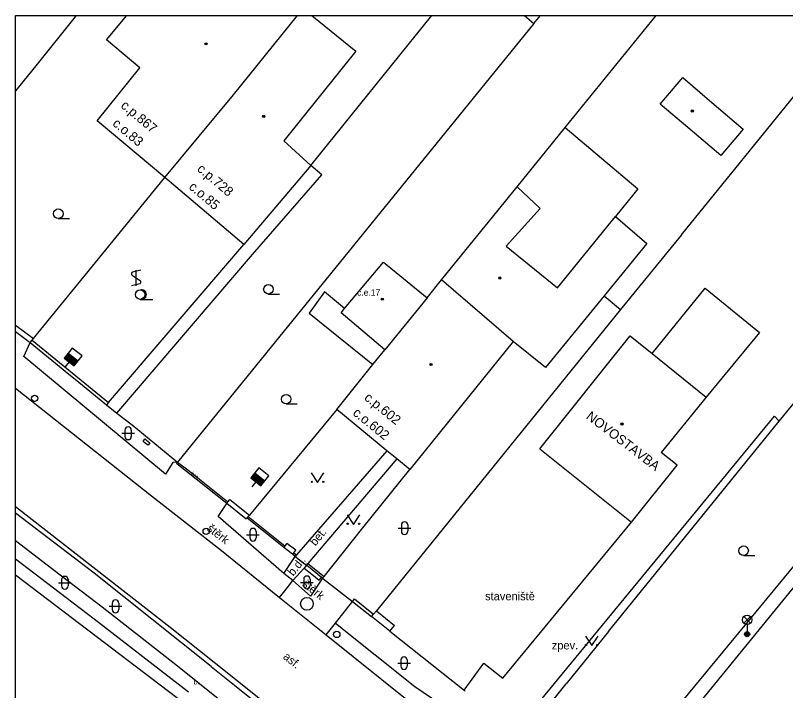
# Model space of a CAD drawing. Extents: x -594386 to -594050, y -1167541 to -1167175.
# Drawn here: x -594386.4 to -594325.8, y -1167228.4 to -1167175.4 of the extents above; entities that cross this region are included whole.
import ezdxf

# ---------------------------------------------------------------- set-up
doc = ezdxf.new("R2010")
doc.units = 0
for name, color, linetype in [('Level 14', 7, 'Continuous'), ('Level 24', 7, 'Continuous'), ('Level 27', 7, 'Continuous'), ('Level 28', 7, 'Continuous'), ('Level 33', 7, 'Continuous'), ('Level 36', 7, 'Continuous'), ('Level 39', 7, 'Continuous'), ('Level 41', 7, 'Continuous'), ('Vrstva 10', 7, 'Continuous'), ('Vrstva 11', 7, 'Continuous'), ('Vrstva 40', 7, 'Continuous'), ('Vrstva 42', 7, 'Continuous'), ('Vrstva 46', 7, 'Continuous'), ('Vrstva 5', 7, 'Continuous'), ('Vrstva 51', 7, 'Continuous'), ('Vrstva 52', 7, 'Continuous'), ('Vrstva 63', 7, 'Continuous'), ('Vrstva 7', 7, 'Continuous'), ('Vrstva 8', 7, 'Continuous')]:
    doc.layers.add(name, color=color, linetype=linetype)

msp = doc.modelspace()

# ---------------------------------------------------------------- linework, layer by layer
at = {"layer": 'Level 14'}
for points in [[(-594373.63, -1167226.53), (-594379.54, -1167221.89), (-594382.84, -1167219.37), (-594386.36, -1167216.691)], [(-594372.76, -1167228.57), (-594380.18, -1167222.84), (-594382.36, -1167221.16), (-594386.36, -1167218.111)], [(-594353.85, -1167242.33), (-594359.75, -1167237.6), (-594370.16, -1167229.3), (-594373.63, -1167226.53)]]:
    msp.add_lwpolyline(points, dxfattribs=at)
at = {"layer": 'Level 24'}
for points in [[(-594363.49, -1167218.6), (-594363.67, -1167218.83)], [(-594363.67, -1167218.83), (-594363.08, -1167219.3), (-594362.49, -1167219.78), (-594362.31, -1167219.55)], [(-594362.31, -1167219.55), (-594363.49, -1167218.6)]]:
    msp.add_lwpolyline(points, dxfattribs=at)
at = {"layer": 'Level 27'}
msp.add_circle((-594363.46, -1167221.63), 0.5, dxfattribs=at)
at = {"layer": 'Level 28'}
for p, q in [((-594382.252, -1167201.977), (-594381.47, -1167202.601)), ((-594382.221, -1167201.938), (-594381.439, -1167202.562)), ((-594382.502, -1167202.29), (-594381.72, -1167202.914)), ((-594382.47, -1167202.251), (-594381.689, -1167202.875)), ((-594382.439, -1167202.212), (-594381.658, -1167202.835)), ((-594382.408, -1167202.172), (-594381.626, -1167202.796)), ((-594382.377, -1167202.133), (-594381.595, -1167202.757)), ((-594382.346, -1167202.094), (-594381.564, -1167202.718)), ((-594382.314, -1167202.055), (-594381.533, -1167202.679)), ((-594382.283, -1167202.016), (-594381.502, -1167202.64)), ((-594382.142, -1167202.641), (-594382.473, -1167203.055)), ((-594367.822, -1167211.69), (-594367.04, -1167212.314)), ((-594367.79, -1167211.651), (-594367.009, -1167212.275)), ((-594367.759, -1167211.612), (-594366.978, -1167212.235)), ((-594367.728, -1167211.572), (-594366.946, -1167212.196)), ((-594367.697, -1167211.533), (-594366.915, -1167212.157)), ((-594367.666, -1167211.494), (-594366.884, -1167212.118)), ((-594367.634, -1167211.455), (-594366.853, -1167212.079)), ((-594367.603, -1167211.416), (-594366.822, -1167212.04)), ((-594367.572, -1167211.377), (-594366.79, -1167212.001)), ((-594367.541, -1167211.338), (-594366.759, -1167211.962)), ((-594367.462, -1167212.041), (-594367.793, -1167212.455))]:
    msp.add_line(p, q, dxfattribs=at)
for points in [[(-594382.533, -1167202.329), (-594381.751, -1167202.953), (-594381.127, -1167202.171), (-594381.909, -1167201.547)], [(-594367.853, -1167211.729), (-594367.071, -1167212.353), (-594366.447, -1167211.571), (-594367.229, -1167210.947)]]:
    msp.add_lwpolyline(points, close=True, dxfattribs=at)
for centre in [(-594384.85, -1167205.49), (-594371.37, -1167215.94), (-594361.11, -1167224.03)]:
    msp.add_circle(centre, 0.25, dxfattribs=at)
at = {"layer": 'Level 33'}
for p, q in [((-594329.135, -1167223.15), (-594328.605, -1167222.62)), ((-594329.135, -1167222.62), (-594328.605, -1167223.15)), ((-594328.87, -1167223.26), (-594328.87, -1167224.01))]:
    msp.add_line(p, q, dxfattribs=at)
for centre, radius in [((-594328.87, -1167222.885), 0.375), ((-594328.87, -1167224.01), 0.2), ((-594328.87, -1167224.01), 0.145), ((-594328.87, -1167224.01), 0.0876)]:
    msp.add_circle(centre, radius, dxfattribs=at)
at = {"layer": 'Level 36'}
for p, q in [((-594382.99, -1167191.375), (-594382.115, -1167191.375)), ((-594377.195, -1167195.826), (-594376.541, -1167196.262)), ((-594376.495, -1167195.419), (-594377.156, -1167195.578)), ((-594376.87, -1167196.669), (-594376.87, -1167195.419)), ((-594376.58, -1167196.507), (-594377.245, -1167196.669)), ((-594376.56, -1167197.725), (-594375.56, -1167197.725)), ((-594366.48, -1167197.305), (-594365.605, -1167197.305)), ((-594365.09, -1167205.935), (-594364.215, -1167205.935)), ((-594377.756, -1167207.986), (-594377.756, -1167208.486)), ((-594377.256, -1167207.986), (-594377.256, -1167208.486)), ((-594378.006, -1167208.236), (-594377.006, -1167208.236)), ((-594356.286, -1167215.686), (-594355.286, -1167215.686)), ((-594356.036, -1167215.436), (-594356.036, -1167215.936)), ((-594355.536, -1167215.436), (-594355.536, -1167215.936)), ((-594368.196, -1167216.206), (-594367.196, -1167216.206)), ((-594367.946, -1167215.956), (-594367.946, -1167216.456)), ((-594367.446, -1167215.956), (-594367.446, -1167216.456)), ((-594329.15, -1167217.835), (-594328.275, -1167217.835)), ((-594382.976, -1167219.976), (-594381.976, -1167219.976)), ((-594382.726, -1167219.726), (-594382.726, -1167220.226)), ((-594382.226, -1167219.726), (-594382.226, -1167220.226)), ((-594363.956, -1167219.946), (-594362.956, -1167219.946)), ((-594363.706, -1167219.696), (-594363.706, -1167220.196)), ((-594363.206, -1167219.696), (-594363.206, -1167220.196)), ((-594378.996, -1167221.826), (-594377.996, -1167221.826)), ((-594378.746, -1167221.576), (-594378.746, -1167222.076)), ((-594378.246, -1167221.576), (-594378.246, -1167222.076)), ((-594356.076, -1167226.036), (-594356.076, -1167226.536)), ((-594355.576, -1167226.036), (-594355.576, -1167226.536)), ((-594356.326, -1167226.286), (-594355.326, -1167226.286))]:
    msp.add_line(p, q, dxfattribs=at)
for points in [[(-594363.12, -1167211.35), (-594362.62, -1167212.1), (-594362.12, -1167211.35)], [(-594360.3, -1167214.64), (-594359.8, -1167215.39), (-594359.3, -1167214.64)], [(-594341.58, -1167224.16), (-594341.08, -1167224.91), (-594340.58, -1167224.16)]]:
    msp.add_lwpolyline(points, dxfattribs=at)
for centre, radius in [((-594382.99, -1167191), 0.375), ((-594366.48, -1167196.93), 0.375), ((-594376.56, -1167197.35), 0.375), ((-594365.09, -1167205.56), 0.375), ((-594363.07, -1167212.05), 0.05), ((-594362.171, -1167212.05), 0.05), ((-594360.25, -1167215.34), 0.05), ((-594359.351, -1167215.34), 0.05), ((-594329.15, -1167217.46), 0.375), ((-594341.53, -1167224.86), 0.05), ((-594340.631, -1167224.86), 0.05)]:
    msp.add_circle(centre, radius, dxfattribs=at)
for centre, radius, start, end in [((-594377.095, -1167195.715), 0.15, 113.96482, 228.0101), ((-594376.644, -1167196.371), 0.15, 295.55354, 46.6612), ((-594376.435, -1167197.35), 0.375, 260.40593, 99.59407), ((-594377.506, -1167207.986), 0.25, 0, 180), ((-594377.506, -1167208.486), 0.25, 180, 0), ((-594355.786, -1167215.436), 0.25, 0, 180), ((-594367.696, -1167215.956), 0.25, 0, 180), ((-594367.696, -1167216.456), 0.25, 180, 0), ((-594355.786, -1167215.936), 0.25, 180, 0), ((-594382.476, -1167219.726), 0.25, 0, 180), ((-594363.456, -1167219.696), 0.25, 0, 180), ((-594382.476, -1167220.226), 0.25, 180, 0), ((-594363.456, -1167220.196), 0.25, 180, 0), ((-594378.496, -1167221.576), 0.25, 0, 180), ((-594378.496, -1167222.076), 0.25, 180, 0), ((-594355.826, -1167226.036), 0.25, 0, 180), ((-594355.826, -1167226.536), 0.25, 180, 0)]:
    msp.add_arc(centre, radius, start, end, dxfattribs=at)
at = {"layer": 'Level 39'}
for centre, radius in [((-594371.39, -1167177.66), 0.09), ((-594371.39, -1167177.66), 0.0398), ((-594333.18, -1167182.94), 0.09), ((-594333.18, -1167182.94), 0.0398), ((-594366.85, -1167183.35), 0.09), ((-594366.85, -1167183.35), 0.0398), ((-594348.3, -1167196.05), 0.09), ((-594348.3, -1167196.05), 0.0398), ((-594357.54, -1167197.71), 0.09), ((-594357.54, -1167197.71), 0.0398), ((-594353.7, -1167202.84), 0.09), ((-594353.7, -1167202.84), 0.0398), ((-594338.71, -1167207.5), 0.09), ((-594338.71, -1167207.5), 0.0398)]:
    msp.add_circle(centre, radius, dxfattribs=at)
at = {"layer": 'Vrstva 10'}
for points in [[(-594288.255, -1167175.43), (-594294.11, -1167182.6), (-594312.38, -1167204.76), (-594325.04, -1167220.12), (-594334.343, -1167231.486)], [(-594386.36, -1167204.709), (-594375.68, -1167213.14), (-594370.17, -1167217.45), (-594365.6, -1167221.12)], [(-594370.74, -1167226.23), (-594374.19, -1167223.49), (-594386.36, -1167214.023)], [(-594365.6, -1167221.12), (-594361.94, -1167224.06)], [(-594361.94, -1167224.06), (-594353.34, -1167230.97)], [(-594347.28, -1167244.92), (-594358.53, -1167235.89), (-594365.15, -1167230.7), (-594370.74, -1167226.23)]]:
    msp.add_lwpolyline(points, dxfattribs=at)
at = {"layer": 'Vrstva 11'}
msp.add_line((-594326.34, -1167207.29), (-594300.428, -1167175.43), dxfattribs=at)
for points in [[(-594378.38, -1167206.65), (-594367.73, -1167194.21), (-594362.28, -1167187.95), (-594363.16, -1167187.22)], [(-594337.77, -1167189.43), (-594339.22, -1167191.21)], [(-594379.04, -1167205.82), (-594368.41, -1167193.42)], [(-594360.5, -1167198.43), (-594362.07, -1167197.13), (-594363.28, -1167198.82), (-594358.28, -1167202.85)], [(-594340.11, -1167197.45), (-594338.81, -1167198.52)], [(-594373.62, -1167210.5), (-594373.98, -1167210.53), (-594374.57, -1167211.45), (-594385.7, -1167202.22), (-594385.19, -1167201.12)], [(-594336.34, -1167201.97), (-594332.08, -1167205.41)], [(-594347.182, -1167231.742), (-594326.73, -1167206.89)], [(-594339.76, -1167223.79), (-594326.34, -1167207.29)], [(-594326.73, -1167206.89), (-594326.34, -1167207.29)], [(-594376.33, -1167208.88), (-594376.18, -1167208.68), (-594375.79, -1167208.98), (-594375.94, -1167209.18), (-594376.14, -1167209.03), (-594376.33, -1167208.88)], [(-594357.17, -1167209.61), (-594364.27, -1167217.79)], [(-594356.4, -1167210.24), (-594363.38, -1167218.47)], [(-594369.75, -1167213.74), (-594373.68, -1167210.65), (-594373.62, -1167210.5)], [(-594359.06, -1167215.65), (-594355.38, -1167211.08)], [(-594365.26, -1167219.26), (-594370.43, -1167214.78), (-594369.75, -1167213.74)], [(-594370.99, -1167226.54), (-594380.17, -1167219.21), (-594386.36, -1167214.509)], [(-594351.108, -1167228.403), (-594349.55, -1167226.28), (-594348.07, -1167227.47), (-594337.95, -1167215.22)], [(-594365.26, -1167219.26), (-594364.37, -1167217.92)], [(-594364.56, -1167219.81), (-594363.67, -1167218.83)], [(-594386.36, -1167219.36), (-594371.16, -1167230.89), (-594358.47, -1167240.9), (-594344.93, -1167251.59)], [(-594364.56, -1167219.81), (-594365.26, -1167219.26)], [(-594365.6, -1167221.12), (-594364.98, -1167220.35), (-594364.56, -1167219.81)], [(-594362.22, -1167219.62), (-594363.18, -1167221.03), (-594364.56, -1167219.81)], [(-594361.2, -1167223.15), (-594359.87, -1167221.44)], [(-594361.94, -1167224.06), (-594361.2, -1167223.15)], [(-594361.2, -1167223.15), (-594354.97, -1167228.11), (-594352.36, -1167229.91)], [(-594370.99, -1167226.54), (-594369.15, -1167228.01), (-594363.93, -1167232.21), (-594354.49, -1167239.67), (-594347.58, -1167245.26)]]:
    msp.add_lwpolyline(points, dxfattribs=at)
at = {"layer": 'Vrstva 5'}
for p, q in [((-594386.35, -1167175.48), (-594386.36, -1167175.481)), ((-594386.309, -1167175.43), (-594386.35, -1167175.48)), ((-594379.19, -1167177.34), (-594377.602, -1167175.43)), ((-594369.22, -1167181.67), (-594364.184, -1167175.43)), ((-594363.064, -1167175.43), (-594359.61, -1167178.24))]:
    msp.add_line(p, q, dxfattribs=at)
for points in [[(-594376.58, -1167179.55), (-594379.19, -1167177.34)], [(-594359.61, -1167178.24), (-594365.28, -1167185.27)], [(-594379.94, -1167183.71), (-594376.58, -1167179.55)], [(-594374.62, -1167188.16), (-594369.22, -1167181.67)], [(-594374.62, -1167188.16), (-594379.94, -1167183.71)], [(-594365.28, -1167185.27), (-594363.16, -1167187.22)], [(-594363.16, -1167187.22), (-594368.41, -1167193.42)], [(-594368.41, -1167193.42), (-594374.62, -1167188.16)], [(-594352.87, -1167196.2), (-594346.95, -1167188.89)], [(-594346.95, -1167188.89), (-594345.13, -1167190.6)], [(-594345.13, -1167190.6), (-594347.8, -1167193.56)], [(-594343.77, -1167196.82), (-594339.22, -1167191.21)], [(-594339.22, -1167191.21), (-594336.74, -1167193.33)], [(-594336.74, -1167193.33), (-594340.11, -1167197.45)], [(-594347.8, -1167193.56), (-594343.77, -1167196.82)], [(-594360.5, -1167198.43), (-594357.45, -1167194.81)], [(-594357.45, -1167194.81), (-594354.01, -1167197.6)], [(-594354.01, -1167197.6), (-594352.87, -1167196.2)], [(-594347.25, -1167201.03), (-594352.87, -1167196.2)], [(-594354.01, -1167197.6), (-594357.33, -1167201.68)], [(-594340.11, -1167197.45), (-594344.72, -1167203.08)], [(-594360.76, -1167198.77), (-594360.5, -1167198.43)], [(-594357.33, -1167201.68), (-594360.76, -1167198.77)], [(-594345.15, -1167209.46), (-594338.05, -1167200.59)], [(-594347.25, -1167201.03), (-594355.38, -1167211.08)], [(-594344.72, -1167203.08), (-594347.25, -1167201.03)], [(-594358.28, -1167202.85), (-594357.33, -1167201.68)], [(-594361.11, -1167206.36), (-594358.28, -1167202.85)], [(-594357.17, -1167209.61), (-594361.11, -1167206.36)], [(-594356.4, -1167210.24), (-594357.17, -1167209.61)], [(-594345.15, -1167209.46), (-594337.95, -1167215.22)], [(-594334.37, -1167210.75), (-594335.63, -1167209.74)], [(-594355.38, -1167211.08), (-594356.4, -1167210.24)], [(-594337.95, -1167215.22), (-594334.37, -1167210.75)]]:
    msp.add_lwpolyline(points, dxfattribs=at)
at = {"layer": 'Vrstva 51'}
for p, q in [((-594363.16, -1167187.22), (-594353.639, -1167175.43)), ((-594346.37, -1167175.43), (-594345.62, -1167176.06)), ((-594345.62, -1167176.06), (-594345.112, -1167175.43)), ((-594343.17, -1167184.23), (-594336.029, -1167175.43)), ((-594334.03, -1167192.65), (-594320.033, -1167175.43))]:
    msp.add_line(p, q, dxfattribs=at)
for points in [[(-594346.95, -1167188.89), (-594343.17, -1167184.23)], [(-594343.17, -1167184.23), (-594337.46, -1167189.04)], [(-594337.46, -1167189.04), (-594337.77, -1167189.43)], [(-594336.34, -1167201.97), (-594332.17, -1167196.85), (-594327.91, -1167200.33), (-594332.08, -1167205.41)], [(-594338.05, -1167200.59), (-594336.34, -1167201.97)], [(-594332.08, -1167205.41), (-594335.63, -1167209.74)]]:
    msp.add_lwpolyline(points, dxfattribs=at)
at = {"layer": 'Vrstva 52'}
for points in [[(-594335.7, -1167182.39), (-594333.93, -1167180.31)], [(-594333.93, -1167180.31), (-594331.82, -1167182.11)], [(-594333.54, -1167184.22), (-594335.7, -1167182.39)], [(-594331.82, -1167182.11), (-594329.18, -1167184.35)], [(-594330.94, -1167186.43), (-594333.54, -1167184.22)], [(-594329.18, -1167184.35), (-594330.94, -1167186.43)]]:
    msp.add_lwpolyline(points, dxfattribs=at)
at = {"layer": 'Vrstva 63'}
msp.add_lwpolyline([(-594386.36, -1167175.43), (-594049.75, -1167175.43), (-594049.75, -1167540.79), (-594386.36, -1167540.79)], close=True, dxfattribs=at)
at = {"layer": 'Vrstva 7'}
for p, q in [((-594381.59, -1167175.43), (-594384.76, -1167179.39)), ((-594384.76, -1167179.39), (-594386.36, -1167181.342)), ((-594386.36, -1167199.742), (-594384.95, -1167200.8)), ((-594386.36, -1167200.246), (-594385.19, -1167201.12))]:
    msp.add_line(p, q, dxfattribs=at)
for points in [[(-594345.62, -1167176.06), (-594373.62, -1167210.5)], [(-594293.29, -1167179.81), (-594294.47, -1167181.2), (-594313.23, -1167204.15), (-594335.22, -1167230.78)], [(-594384.95, -1167200.8), (-594374.62, -1167188.16)], [(-594334.03, -1167192.65), (-594338.81, -1167198.52)], [(-594338.81, -1167198.52), (-594358, -1167222.18)], [(-594385.04, -1167200.92), (-594384.95, -1167200.8)], [(-594385.19, -1167201.12), (-594385.04, -1167200.92)], [(-594385.19, -1167201.12), (-594383.21, -1167202.74), (-594382.44, -1167203.37), (-594382.04, -1167203.69), (-594381.66, -1167204), (-594379.2, -1167206.01)], [(-594385.04, -1167200.92), (-594379.04, -1167205.82)], [(-594379.04, -1167205.82), (-594379.2, -1167206.01)], [(-594361.11, -1167206.36), (-594367.98, -1167214.66)], [(-594377.18, -1167207.58), (-594373.62, -1167210.5)], [(-594369.66, -1167213.62), (-594369.5, -1167213.43)], [(-594369.5, -1167213.43), (-594367.98, -1167214.66)], [(-594369.75, -1167213.74), (-594369.66, -1167213.62)], [(-594368.17, -1167214.89), (-594368.23, -1167214.97), (-594369.75, -1167213.74)], [(-594368.07, -1167214.76), (-594367.98, -1167214.66)], [(-594368.17, -1167214.89), (-594368.07, -1167214.76)], [(-594365.28, -1167217.2), (-594368.17, -1167214.89)], [(-594368.07, -1167214.76), (-594365.18, -1167217.07)], [(-594362.11, -1167219.49), (-594359.06, -1167215.65)], [(-594365.18, -1167217.07), (-594365.28, -1167217.2)], [(-594365.04, -1167216.88), (-594365.18, -1167217.07)], [(-594364.34, -1167217.42), (-594365.04, -1167216.88)], [(-594364.58, -1167217.74), (-594364.93, -1167217.47), (-594365.28, -1167217.2)], [(-594364.58, -1167217.74), (-594364.49, -1167217.62)], [(-594364.37, -1167217.92), (-594364.58, -1167217.74)], [(-594364.49, -1167217.62), (-594364.34, -1167217.42)], [(-594364.49, -1167217.62), (-594364.27, -1167217.79)], [(-594364.27, -1167217.79), (-594364.37, -1167217.92)], [(-594363.49, -1167218.6), (-594363.38, -1167218.47)], [(-594363.38, -1167218.47), (-594362.11, -1167219.49)], [(-594362.22, -1167219.62), (-594362.31, -1167219.55)], [(-594362.11, -1167219.49), (-594362.22, -1167219.62)], [(-594359.87, -1167221.44), (-594359.71, -1167221.25)], [(-594359.71, -1167221.25), (-594358.22, -1167222.45)], [(-594358.37, -1167222.63), (-594358.22, -1167222.45)], [(-594358.22, -1167222.45), (-594358, -1167222.18)], [(-594358, -1167222.18), (-594356.58, -1167223.33)], [(-594356.95, -1167223.78), (-594358.37, -1167222.63)], [(-594356.95, -1167223.78), (-594356.58, -1167223.33)], [(-594356.95, -1167223.78), (-594351.108, -1167228.403)], [(-594339.76, -1167223.79), (-594343.09, -1167227.92)], [(-594346.59, -1167232.28), (-594343.09, -1167227.92)], [(-594351.108, -1167228.403), (-594351.01, -1167228.48)]]:
    msp.add_lwpolyline(points, dxfattribs=at)
at = {"layer": 'Vrstva 8'}
for points in [[(-594379.2, -1167206.01), (-594378.38, -1167206.65)], [(-594378.38, -1167206.65), (-594377.18, -1167207.58)], [(-594373.62, -1167210.5), (-594372.8, -1167211.11), (-594369.66, -1167213.62)], [(-594364.37, -1167217.92), (-594363.49, -1167218.6)], [(-594362.22, -1167219.62), (-594359.87, -1167221.44)], [(-594359.87, -1167221.44), (-594358.37, -1167222.63)]]:
    msp.add_lwpolyline(points, dxfattribs=at)

# ---------------------------------------------------------------- texts
at = {"layer": 'Level 41'}
msp.add_text('NOVOSTAVBA', height=0.75, rotation=322.64046, dxfattribs=at).set_placement((-594341.58, -1167207.04))
at = {"layer": 'Vrstva 40'}
for s, height, rotation, p in [('bet.', 0.3, 321.82346, (-594372.6, -1167211.47)), ('štěrk', 0.65, 321.8828, (-594371.36, -1167215.82)), ('bet.', 0.65, 50.69443, (-594362.79, -1167217.13)), ('b.dl.', 0.65, 51.23, (-594364.53, -1167219.49)), ('štěrk', 0.65, 321.37, (-594363.88, -1167220.18)), ('asf.', 0.65, 321, (-594365.38, -1167225.88))]:
    msp.add_text(s, height=height, rotation=rotation, dxfattribs=at).set_placement(p)
for s, height, p in [('zpev.', 0.65, (-594344.22, -1167225.21)), ('b.', 0.4, (-594372.36, -1167227.96))]:
    msp.add_text(s, height=height, dxfattribs=at).set_placement(p)
at = {"layer": 'Vrstva 42'}
msp.add_text('staveniště', height=0.65, dxfattribs=at).set_placement((-594349.46, -1167221.35))
at = {"layer": 'Vrstva 46'}
for s, rotation, p in [('c.p.867', 319.86726, (-594378.137, -1167182.603)), ('c.o.83', 319.86726, (-594378.79, -1167184.009)), ('c.p.728', 319.86726, (-594372.146, -1167187.58)), ('c.o.85', 319.86726, (-594372.79, -1167188.989)), ('c.p.602', 320.91781, (-594359.012, -1167205.549)), ('c.o.602', 320.91781, (-594359.913, -1167206.745))]:
    msp.add_text(s, height=0.75, rotation=rotation, dxfattribs=at).set_placement(p)
msp.add_text('c.e.17', height=0.5, dxfattribs=at).set_placement((-594359.515, -1167197.435))

doc.saveas('drawing.dxf')
